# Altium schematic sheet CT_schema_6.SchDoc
size 242 x 245 mm
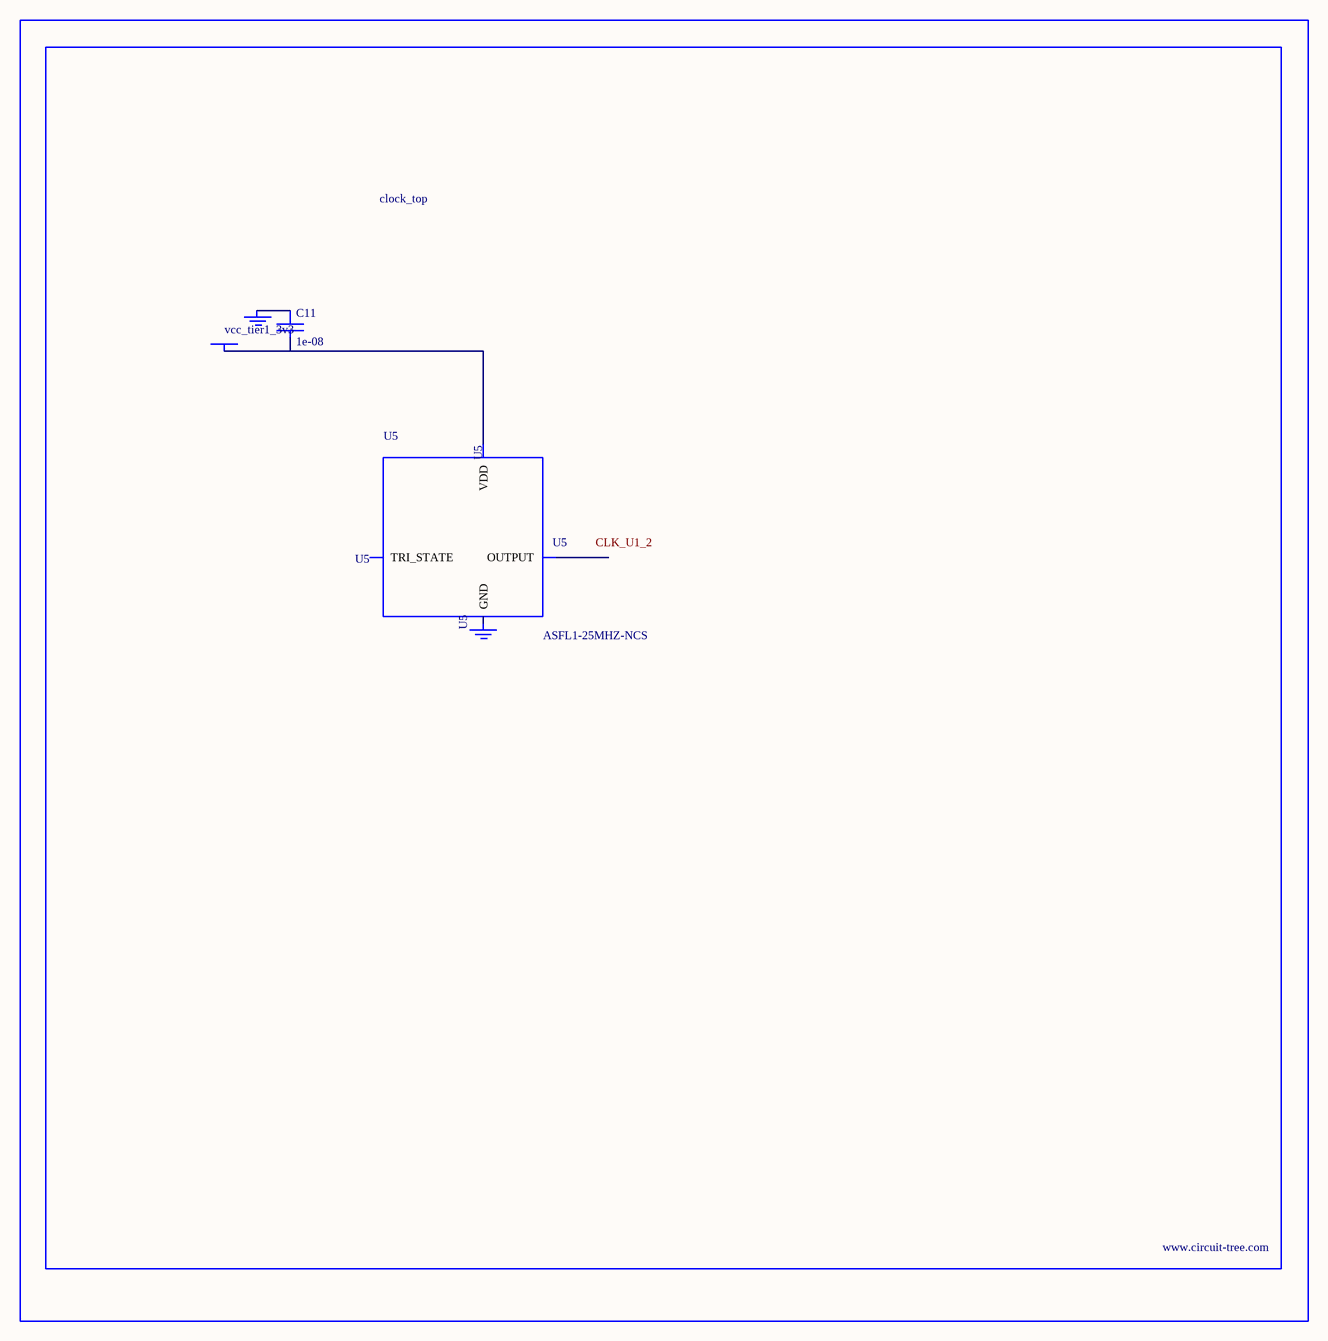
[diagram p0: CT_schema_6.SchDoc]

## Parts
BORDER5  (no value)
C11  1e-08  [C0402]
GND_INSTANCE_5_0  (no value)
GND_INSTANCE_5_1  (no value)
POWER_INSTANCE_5_0  vcc_tier1_3v3
U5  ASFL1-25MHZ-NCS  [ASFL1]

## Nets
NetC11_1: C11.1 GND_INSTANCE_5_0.0(GND)
NetC11_2: C11.2 POWER_INSTANCE_5_0.0(PWR) U5.4(VDD)

Not connected (* = marked no-connect by the designer): GND_INSTANCE_5_1 0(GND); U5 1(TRI_STATE) 2(GND) 3(OUTPUT)

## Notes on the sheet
- Labels drawn without touching a wire or pin: CLK_U1_2

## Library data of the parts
BORDER5 = BORDER_PAGE5
C11 = C0402C103K3RAC
GND_INSTANCE_5_0 GND_INSTANCE_5_1 = GND
POWER_INSTANCE_5_0 = PWR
